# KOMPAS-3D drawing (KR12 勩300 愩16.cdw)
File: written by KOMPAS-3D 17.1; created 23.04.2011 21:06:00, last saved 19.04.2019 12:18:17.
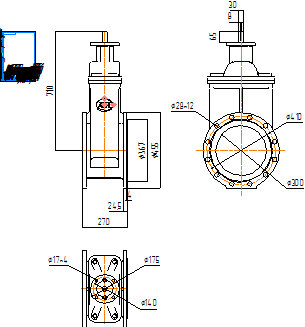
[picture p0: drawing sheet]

Sheet 1: A4, portrait

Title block, sheet 1: name: KR12 Ду300 Ру16; material: Внимание! Данный продукт является объектом авторского права ООО «Торговый Дом АДЛ». / Запрещается изменение, копирование, распространение / (в том числе путем копирования на другие сайты и ресурсы в Интернете) / или любое иное использование информации и объектов без предварительного / согласия правообладателя (ООО «Торговый Дом АДЛ»).; scale: 1:1; sheets: 1; organisation: ООО "Торговый дом АДЛ"; sheet format: A4; stored path: \\adlc.lan\data\АДЛ_ПКД\3D-модели\ADL production\Клиновые задвижки серии KR ГРАНАР\Клиновые задвижки KR12\KOMPAS 2D\KR12 Ду300 Ру16.cdw

Views: Спереди 4, Проекционный вид 5
Dimensions and other numbers on the sheet: 710; 270; 24,5; 4; 367; 455; 175; 17; 140; 1:1; 1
